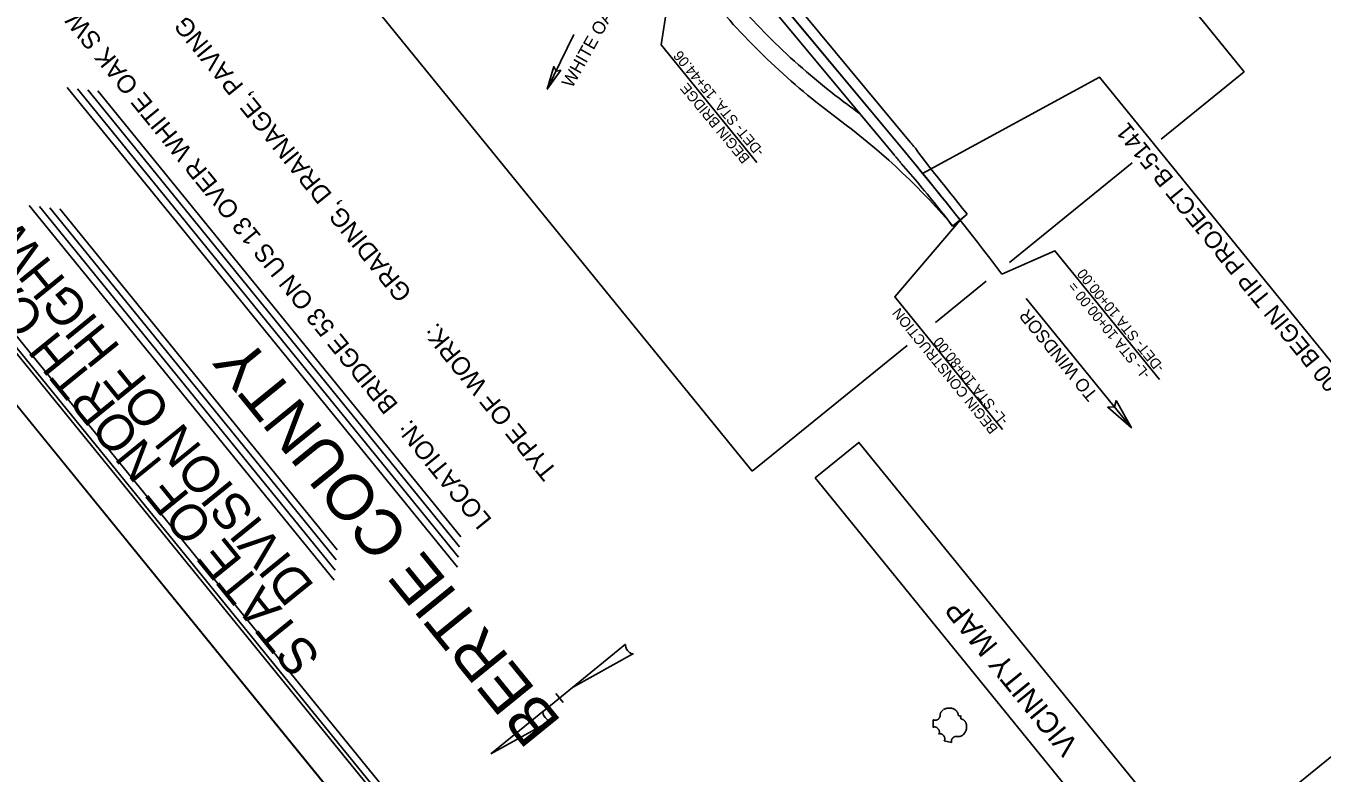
# Model space of a CAD drawing. Extents: x 2596486 to 2602076, y 851390 to 856110.
# Drawn here: x 2597251 to 2598768, y 852253 to 853129 of the extents above; entities that cross this region are included whole.
import ezdxf

# ---------------------------------------------------------------- set-up
doc = ezdxf.new("R2010")
doc.units = 0
for name, color, linetype in [('Default', 7, 'Continuous'), ('Old_Level_1', 7, 'Continuous'), ('Prop Dimension', 7, 'Continuous'), ('Prop Dimension Text', 7, 'Continuous'), ('Prop Horizontal Alignment', 7, 'Continuous'), ('Prop North Arrow for Plan Sheets CELL', 7, 'Continuous'), ('Prop Shade Light', 7, 'Continuous'), ('Prop Terminator CELL', 7, 'Continuous'), ('Sheet Cutting Line CELL', 7, 'Continuous'), ('Sheet Data Field CELL', 7, 'Continuous'), ('Sheet Data Text CELL', 7, 'Continuous'), ('Sheet Plot Border Inside CELL', 7, 'Continuous'), ('Sheet Plot Border Outside CELL', 7, 'Continuous'), ('Sheet Title CELL', 7, 'Continuous')]:
    doc.layers.add(name, color=color, linetype=linetype)

msp = doc.modelspace()

# ---------------------------------------------------------------- linework, layer by layer
at = {"layer": 'Default'}
for p, q in [((2598320.8, 852320.3), (2598320.9, 852320.7)), ((2598320.8, 852319.8), (2598320.8, 852320.3)), ((2598320.9, 852321.6), (2598321, 852322)), ((2598320.9, 852321.3), (2598320.9, 852321.6)), ((2598320.9, 852320.7), (2598320.9, 852321.3)), ((2598321, 852322), (2598321.1, 852322.6)), ((2598321.1, 852322.9), (2598321.2, 852323.2)), ((2598321.1, 852322.6), (2598321.1, 852322.9)), ((2598321.2, 852323.2), (2598321.4, 852323.6)), ((2598321.4, 852323.6), (2598321.5, 852323.9)), ((2598321.5, 852323.9), (2598321.6, 852324.1)), ((2598321.6, 852324.1), (2598321.9, 852324.7)), ((2598321.9, 852324.7), (2598322.3, 852325.2)), ((2598322.3, 852325.2), (2598322.4, 852325.5)), ((2598322.4, 852325.5), (2598322.9, 852326)), ((2598322.9, 852326), (2598323.1, 852326.3)), ((2598323.1, 852326.3), (2598323.6, 852326.8)), ((2598323.6, 852326.8), (2598324.3, 852327.3)), ((2598324.9, 852327.7), (2598325.7, 852328.2)), ((2598325.7, 852328.2), (2598326.2, 852328.4)), ((2598326.2, 852328.4), (2598326.8, 852328.7)), ((2598326.8, 852328.7), (2598327.3, 852328.9)), ((2598327.3, 852328.9), (2598328.2, 852329.1)), ((2598328.2, 852329.1), (2598328.8, 852329.3)), ((2598328.8, 852329.3), (2598329.6, 852329.4)), ((2598329.6, 852329.4), (2598330.1, 852329.5)), ((2598330.1, 852329.5), (2598330.6, 852329.5)), ((2598330.6, 852329.5), (2598331.2, 852329.6)), ((2598331.2, 852329.6), (2598331.9, 852329.6)), ((2598331.9, 852329.6), (2598332.7, 852329.5)), ((2598332.7, 852329.5), (2598333.3, 852329.5)), ((2598333.3, 852329.5), (2598334, 852329.4)), ((2598334, 852329.4), (2598334.4, 852329.3)), ((2598334.4, 852329.3), (2598335, 852329.1)), ((2598335, 852329.1), (2598335.8, 852328.9)), ((2598335.8, 852328.9), (2598336.4, 852328.6)), ((2598336.4, 852328.6), (2598337, 852328.4)), ((2598337, 852328.4), (2598337.5, 852328.1)), ((2598337.5, 852328.1), (2598338.1, 852327.8)), ((2598338.1, 852327.8), (2598338.9, 852327.2)), ((2598338.9, 852327.2), (2598339.2, 852326.9)), ((2598339.2, 852326.9), (2598339.6, 852326.6)), ((2598339.6, 852326.6), (2598339.9, 852326.3)), ((2598339.9, 852326.3), (2598340.2, 852326)), ((2598340.2, 852326), (2598340.5, 852325.6)), ((2598340.5, 852325.6), (2598340.8, 852325.1)), ((2598340.8, 852325.1), (2598341.1, 852324.7)), ((2598341.1, 852324.7), (2598341.3, 852324.2)), ((2598341.3, 852324.2), (2598341.6, 852323.7)), ((2598341.6, 852323.7), (2598341.7, 852323.1)), ((2598341.7, 852323.1), (2598341.9, 852322.6)), ((2598341.9, 852322.6), (2598342, 852321.5)), ((2598342, 852321.5), (2598342, 852321.3)), ((2598342, 852321.3), (2598342.1, 852321.1)), ((2598342.1, 852321.1), (2598342.3, 852320.9)), ((2598342.3, 852320.9), (2598342.5, 852320.7)), ((2598342.5, 852320.7), (2598342.9, 852320.5)), ((2598342.9, 852320.5), (2598343.1, 852320.4)), ((2598343.1, 852320.4), (2598343.4, 852320.3)), ((2598343.4, 852320.3), (2598343.6, 852320.3)), ((2598344.8, 852320.2), (2598345, 852320.3)), ((2598345, 852320.3), (2598345.3, 852320.4)), ((2598345.3, 852320.4), (2598345.6, 852320.5)), ((2598345.6, 852320.5), (2598345.3, 852320.2)), ((2598312.8, 852306.9), (2598312.7, 852315.9)), ((2598312.7, 852315.9), (2598312.8, 852315.8)), ((2598312.8, 852315.8), (2598313.2, 852315.7)), ((2598312.9, 852307), (2598312.8, 852306.9)), ((2598313.1, 852307.1), (2598312.9, 852307)), ((2598313.4, 852307.3), (2598313.1, 852307.1)), ((2598313.2, 852315.7), (2598313.6, 852315.5)), ((2598313.7, 852307.4), (2598313.4, 852307.3)), ((2598313.6, 852315.5), (2598314.1, 852315.4)), ((2598314, 852307.4), (2598313.7, 852307.4)), ((2598314.3, 852307.4), (2598314, 852307.4)), ((2598314.1, 852315.4), (2598314.4, 852315.3)), ((2598314.7, 852307.4), (2598314.3, 852307.4)), ((2598314.4, 852315.3), (2598314.7, 852315.3)), ((2598314.7, 852315.3), (2598315, 852315.3)), ((2598315.1, 852307.4), (2598314.7, 852307.4)), ((2598315, 852315.3), (2598315.2, 852315.3)), ((2598315.5, 852307.3), (2598315.1, 852307.4)), ((2598315.2, 852315.3), (2598315.6, 852315.3)), ((2598315.8, 852307.2), (2598315.5, 852307.3)), ((2598315.6, 852315.3), (2598315.9, 852315.3)), ((2598316.3, 852307), (2598315.8, 852307.2)), ((2598315.9, 852315.3), (2598316.3, 852315.4)), ((2598316.3, 852315.4), (2598316.6, 852315.5)), ((2598316.6, 852306.8), (2598316.3, 852307)), ((2598316.6, 852315.5), (2598317.1, 852315.6)), ((2598317, 852306.6), (2598316.6, 852306.8)), ((2598317.3, 852306.3), (2598317, 852306.6)), ((2598317.1, 852315.6), (2598317.5, 852315.8)), ((2598317.6, 852306.1), (2598317.3, 852306.3)), ((2598317.5, 852315.8), (2598317.8, 852315.9)), ((2598317.9, 852305.9), (2598317.6, 852306.1)), ((2598317.8, 852315.9), (2598318.3, 852316.3)), ((2598318.2, 852305.6), (2598317.9, 852305.9)), ((2598318.4, 852305.3), (2598318.2, 852305.6)), ((2598318.3, 852316.3), (2598318.6, 852316.4)), ((2598318.6, 852305), (2598318.4, 852305.3)), ((2598318.6, 852316.4), (2598318.8, 852316.6)), ((2598318.8, 852316.6), (2598319, 852316.8)), ((2598319, 852316.8), (2598319.2, 852317)), ((2598319.2, 852317), (2598319.4, 852317.3)), ((2598319.4, 852317.3), (2598319.6, 852317.5)), ((2598319.6, 852317.5), (2598319.8, 852317.8)), ((2598319.8, 852317.8), (2598320.1, 852318.1)), ((2598320.1, 852318.1), (2598320.3, 852318.5)), ((2598320.3, 852318.5), (2598320.5, 852319.1)), ((2598320.5, 852319.1), (2598320.8, 852319.8)), ((2598343.6, 852320.3), (2598343.9, 852320.2)), ((2598343.9, 852320.2), (2598344.2, 852320.2)), ((2598344.2, 852320.2), (2598344.4, 852320.2)), ((2598344.4, 852320.2), (2598344.8, 852320.2)), ((2598345, 852319), (2598344.9, 852318.7)), ((2598344.9, 852318.7), (2598344.9, 852318.3)), ((2598344.9, 852318.3), (2598345, 852318)), ((2598345.1, 852319.6), (2598345, 852319.3)), ((2598345, 852319.3), (2598345, 852319)), ((2598345, 852318), (2598345, 852317.7)), ((2598345, 852317.7), (2598345.1, 852317.5)), ((2598345.2, 852319.9), (2598345.1, 852319.6)), ((2598345.1, 852317.5), (2598345.2, 852317.3)), ((2598345.3, 852320.2), (2598345.2, 852319.9)), ((2598345.2, 852317.3), (2598345.3, 852317.1)), ((2598345.3, 852317.1), (2598345.4, 852317)), ((2598345.4, 852317), (2598345.6, 852316.8)), ((2598345.6, 852316.8), (2598346, 852316.7)), ((2598346, 852316.7), (2598346.4, 852316.6)), ((2598346.4, 852316.6), (2598346.7, 852316.5)), ((2598346.7, 852316.5), (2598347.1, 852316.3)), ((2598347.1, 852316.3), (2598347.4, 852316.2)), ((2598347.4, 852316.2), (2598347.7, 852316)), ((2598347.7, 852316), (2598348.1, 852315.8)), ((2598348.1, 852315.8), (2598348.5, 852315.5)), ((2598348.5, 852315.5), (2598348.8, 852315.2)), ((2598348.8, 852315.2), (2598349.1, 852315)), ((2598349.1, 852315), (2598349.4, 852314.7)), ((2598349.4, 852314.7), (2598349.7, 852314.4)), ((2598349.7, 852314.4), (2598349.9, 852314.1)), ((2598349.9, 852314.1), (2598350.1, 852313.8)), ((2598350.1, 852313.8), (2598350.4, 852313.4)), ((2598350.4, 852313.4), (2598350.6, 852312.9)), ((2598350.6, 852312.9), (2598350.8, 852312.5)), ((2598350.8, 852312.5), (2598351, 852312.1)), ((2598351, 852312.1), (2598351.2, 852311.6)), ((2598351.2, 852311.6), (2598351.4, 852311.1)), ((2598351.4, 852311.1), (2598351.6, 852310.4)), ((2598351.6, 852305.2), (2598351.4, 852304.2)), ((2598351.6, 852310.4), (2598351.7, 852309.9)), ((2598351.7, 852305.8), (2598351.6, 852305.2)), ((2598351.7, 852309.9), (2598351.8, 852309.1)), ((2598351.9, 852306.7), (2598351.7, 852305.8)), ((2598351.8, 852309.1), (2598351.9, 852308.1)), ((2598351.9, 852308.1), (2598351.9, 852307.3)), ((2598351.9, 852307.3), (2598351.9, 852306.7)), ((2598318.8, 852304.8), (2598318.6, 852305)), ((2598319.1, 852304.5), (2598318.8, 852304.8)), ((2598319.2, 852304.2), (2598319.1, 852304.5)), ((2598319.4, 852303.8), (2598319.2, 852304.2)), ((2598319.5, 852299.3), (2598319.2, 852299)), ((2598319.2, 852299), (2598319.4, 852299.3)), ((2598319.6, 852303.5), (2598319.4, 852303.8)), ((2598319.4, 852299.3), (2598319.5, 852299.4)), ((2598319.5, 852299.4), (2598319.7, 852299.6)), ((2598319.6, 852299.4), (2598319.5, 852299.3)), ((2598319.7, 852303.1), (2598319.6, 852303.5)), ((2598320.1, 852299.5), (2598319.6, 852299.4)), ((2598319.8, 852302.9), (2598319.7, 852303.1)), ((2598319.7, 852299.6), (2598319.8, 852299.8)), ((2598319.9, 852302.6), (2598319.8, 852302.9)), ((2598319.8, 852299.8), (2598319.9, 852300.1)), ((2598320.1, 852301.9), (2598319.9, 852302.6)), ((2598319.9, 852300.1), (2598320, 852300.4)), ((2598320, 852300.4), (2598320.1, 852300.9)), ((2598320.1, 852301.4), (2598320.1, 852301.9)), ((2598320.1, 852301.1), (2598320.1, 852301.4)), ((2598320.1, 852300.9), (2598320.1, 852301.1)), ((2598320.3, 852299.5), (2598320.1, 852299.5)), ((2598320.5, 852299.6), (2598320.3, 852299.5)), ((2598321, 852299.6), (2598320.5, 852299.6)), ((2598321.5, 852299.5), (2598321, 852299.6)), ((2598321.8, 852299.4), (2598321.5, 852299.5)), ((2598322.2, 852299.3), (2598321.8, 852299.4)), ((2598322.7, 852299.1), (2598322.2, 852299.3)), ((2598323, 852298.9), (2598322.7, 852299.1)), ((2598323.4, 852298.7), (2598323, 852298.9)), ((2598323.7, 852298.5), (2598323.4, 852298.7)), ((2598324.3, 852297.9), (2598323.7, 852298.5)), ((2598324.8, 852297.4), (2598324.3, 852297.9)), ((2598325.3, 852296.9), (2598324.8, 852297.4)), ((2598325.6, 852296.3), (2598325.3, 852296.9)), ((2598325.5, 852291.2), (2598325.8, 852291.4)), ((2598334.4, 852289.3), (2598325.5, 852291.2)), ((2598325.9, 852295.7), (2598325.6, 852296.3)), ((2598325.8, 852291.4), (2598326, 852291.7)), ((2598326.2, 852295.2), (2598325.9, 852295.7)), ((2598326, 852291.7), (2598326.1, 852291.8)), ((2598326.1, 852291.8), (2598326.3, 852292.2)), ((2598326.3, 852294.6), (2598326.2, 852295.2)), ((2598326.4, 852294.1), (2598326.3, 852294.6)), ((2598326.3, 852292.2), (2598326.4, 852292.6)), ((2598326.5, 852293.7), (2598326.4, 852294.1)), ((2598326.4, 852292.6), (2598326.5, 852293.2)), ((2598326.5, 852293.2), (2598326.5, 852293.7)), ((2598334.2, 852291.5), (2598334.1, 852291)), ((2598334.1, 852291), (2598334.1, 852290.6)), ((2598334.1, 852290.6), (2598334.2, 852290.3)), ((2598334.3, 852291.9), (2598334.2, 852291.5)), ((2598334.2, 852290.3), (2598334.2, 852289.9)), ((2598334.4, 852292.4), (2598334.3, 852291.9)), ((2598334.6, 852292.9), (2598334.4, 852292.4)), ((2598334.8, 852293.3), (2598334.6, 852292.9)), ((2598335, 852293.7), (2598334.8, 852293.3)), ((2598335.3, 852294), (2598335, 852293.7)), ((2598335.6, 852294.4), (2598335.3, 852294)), ((2598335.9, 852294.8), (2598335.6, 852294.4)), ((2598336.2, 852295), (2598335.9, 852294.8)), ((2598336.6, 852295.3), (2598336.2, 852295)), ((2598337, 852295.6), (2598336.6, 852295.3)), ((2598337.4, 852295.8), (2598337, 852295.6)), ((2598337.7, 852295.9), (2598337.4, 852295.8)), ((2598338.1, 852296.1), (2598337.7, 852295.9)), ((2598338.5, 852296.2), (2598338.1, 852296.1)), ((2598338.9, 852296.3), (2598338.5, 852296.2)), ((2598339.2, 852296.3), (2598338.9, 852296.3)), ((2598339.6, 852296.4), (2598339.2, 852296.3)), ((2598340, 852296.4), (2598339.6, 852296.4)), ((2598340.4, 852296.4), (2598340, 852296.4)), ((2598340.9, 852296.3), (2598340.4, 852296.4)), ((2598341.4, 852296.2), (2598340.9, 852296.3)), ((2598341.9, 852296.1), (2598341.4, 852296.2)), ((2598342.4, 852296.1), (2598341.9, 852296.1)), ((2598342.9, 852296.1), (2598342.4, 852296.1)), ((2598343.4, 852296.2), (2598342.9, 852296.1)), ((2598343.8, 852296.2), (2598343.4, 852296.2)), ((2598344.3, 852296.3), (2598343.8, 852296.2)), ((2598344.8, 852296.5), (2598344.3, 852296.3)), ((2598345.3, 852296.7), (2598344.8, 852296.5)), ((2598345.6, 852296.8), (2598345.3, 852296.7)), ((2598346.1, 852297), (2598345.6, 852296.8)), ((2598346.6, 852297.3), (2598346.1, 852297)), ((2598347.1, 852297.7), (2598346.6, 852297.3)), ((2598347.4, 852297.9), (2598347.1, 852297.7)), ((2598347.9, 852298.3), (2598347.4, 852297.9)), ((2598348.3, 852298.7), (2598347.9, 852298.3)), ((2598348.7, 852299.2), (2598348.3, 852298.7)), ((2598349, 852299.5), (2598348.7, 852299.2)), ((2598349.4, 852300), (2598349, 852299.5)), ((2598349.6, 852300.3), (2598349.4, 852300)), ((2598349.9, 852300.8), (2598349.6, 852300.3)), ((2598350.2, 852301.3), (2598349.9, 852300.8)), ((2598350.5, 852301.9), (2598350.2, 852301.3)), ((2598350.8, 852302.3), (2598350.5, 852301.9)), ((2598351, 852303), (2598350.8, 852302.3)), ((2598351.2, 852303.5), (2598351, 852303)), ((2598351.4, 852304.2), (2598351.2, 852303.5)), ((2598334.2, 852289.9), (2598334.3, 852289.5)), ((2598334.3, 852289.5), (2598334.4, 852289.3))]:
    msp.add_line(p, q, dxfattribs=at)
at = {"layer": 'Old_Level_1'}
for p, q in [((2598676.9, 853075), (2597979.3, 853933.2)), ((2598101, 852606.9), (2597403.5, 853465.1)), ((2597891.9, 853118.6), (2597861, 853054.4)), ((2598676.9, 853075), (2598579.6, 852995.9)), ((2598545.9, 852968.4), (2598402, 852851.5)), ((2598374.9, 852829.5), (2598315.4, 852781.2)), ((2598421.7, 852809.4), (2598544.9, 852657.9)), ((2598282.2, 852754.2), (2598101, 852606.9))]:
    msp.add_line(p, q, dxfattribs=at)
msp.add_lwpolyline([(2598918.6, 852562.8), (2598507.6, 853068.5), (2598300.4, 852955.8)], dxfattribs=at)
msp.add_lwpolyline([(2598563.8, 852120.3), (2598174.7, 852599.1), (2598225.8, 852640.7), (2598614.9, 852161.8)], close=True, dxfattribs=at)
at = {"layer": 'Prop Dimension'}
for points in [[(2598393.9, 852655.9), (2598267.7, 852811.3), (2598344.2, 852901.2)], [(2598577.9, 852714.4), (2598455.3, 852865.1), (2598393.1, 852837.9)]]:
    msp.add_lwpolyline(points, dxfattribs=at)
at = {"layer": 'Prop Dimension Text'}
msp.add_lwpolyline([(2598106.5, 852968.5), (2597994.5, 853106.3), (2598012.8, 853224.2)], dxfattribs=at)
at = {"layer": 'Prop Horizontal Alignment'}
msp.add_line((2598276.5, 852984.9), (2597890.8, 853449.4), dxfattribs=at)
msp.add_arc((2595067.5, 850320.2), 4171.2, 37.1289, 39.7067, dxfattribs=at)
at = {"layer": 'Prop North Arrow for Plan Sheets CELL'}
for p, q in [((2597952.6, 852404.2), (2597890.6, 852353.7)), ((2597890.6, 852353.7), (2597961.9, 852393.3)), ((2597890.6, 852353.7), (2597856, 852325.6)), ((2597879.5, 852336), (2597870.9, 852346.6)), ((2597875.8, 852340.6), (2597879.6, 852336)), ((2597879.6, 852336), (2597879.6, 852335.9)), ((2597794.8, 852275.8), (2597857.9, 852327.1)), ((2597857.9, 852327.1), (2597856.1, 852325.6)), ((2597864.8, 852314.7), (2597794.9, 852275.8)), ((2597794.8, 852275.8), (2597794.9, 852275.8)), ((2597794.8, 852275.8), (2597794.9, 852275.8))]:
    msp.add_line(p, q, dxfattribs=at)
for centre, start_param, end_param in [((2597957.6, 852399.1), 0.201328, 3.141593), ((2597861, 852320.6), 0.216388, 2.908219)]:
    msp.add_ellipse(centre, major_axis=(-4.5, 5.61), ratio=0.461098, start_param=start_param, end_param=end_param, dxfattribs=at)
at = {"layer": 'Prop Shade Light'}
for p, q in [((2598276.5, 852984.9), (2598069.3, 853234.4)), ((2598069.3, 853234.4), (2598276.5, 852984.9)), ((2598285.7, 852992.6), (2598078.6, 853242.1)), ((2598060.1, 853226.7), (2598267.3, 852977.3)), ((2598267.3, 852977.3), (2598227.8, 853024.8)), ((2598308.7, 852962.6), (2598293.8, 852982.8)), ((2598275.3, 852967.6), (2598291.8, 852948.8)), ((2598291.8, 852948.8), (2598275.3, 852967.6)), ((2598330.7, 852900.3), (2598335.6, 852894.2)), ((2598335.5, 852894.1), (2598352.7, 852908.1)), ((2598335.6, 852894.2), (2598344.2, 852901.2)), ((2598344.2, 852901.2), (2598352.5, 852908))]:
    msp.add_line(p, q, dxfattribs=at)
msp.add_lwpolyline([(2598352.5, 852908), (2598352.5, 852908)], dxfattribs=at)
for centre, radius, start, end in [((2598702.4, 853697.7), 823, 219.7067, 233.4707), ((2598702.4, 853697.7), 843, 219.7067, 233.4707), ((2597710.7, 852359), 843, 52.1621, 53.4707), ((2597710.7, 852359), 823, 41.1205, 53.4707), ((2595076.8, 850327.8), 4171.2, 39.5327, 39.7067), ((2595067.5, 850320.2), 4159.2, 39.5337, 39.7067), ((2595067.5, 850320.2), 4159.2, 39.5337, 39.7067), ((2595067.5, 850320.2), 4171.2, 38.2278, 39.7067), ((2595067.5, 850320.2), 4171.2, 38.2278, 39.7067), ((2595067.5, 850320.2), 4181.9, 38.2302, 39.1893), ((2595067.5, 850320.2), 4160, 38.2252, 39.1893), ((2595067.5, 850320.2), 4160, 38.2252, 39.1893)]:
    msp.add_arc(centre, radius, start, end, dxfattribs=at)
at = {"layer": 'Prop Terminator CELL'}
for points in [[(2597876.9, 853076.7), (2597861, 853054.4), (2597868.5, 853080.9), (2597871.3, 853075.8)], [(2598527, 852689.7), (2598544.9, 852657.9), (2598517.1, 852682), (2598525, 852682.4)]]:
    msp.add_lwpolyline(points, close=True, dxfattribs=at)
at = {"layer": 'Sheet Cutting Line CELL'}
msp.add_line((2598291.5, 851390.2), (2596485.9, 853611.8), dxfattribs=at)
at = {"layer": 'Sheet Plot Border Inside CELL'}
msp.add_lwpolyline([(2599699.1, 852562.7), (2597912.3, 854761.2), (2596520.4, 853629.9), (2598307.2, 851431.4)], close=True, dxfattribs=at)
at = {"layer": 'Sheet Plot Border Outside CELL'}
msp.add_lwpolyline([(2596485.9, 853611.8), (2598291.5, 851390.2), (2599742.7, 852569.6), (2597937, 854791.2)], close=True, dxfattribs=at)
at = {"layer": 'Sheet Title CELL'}
for p, q in [((2597755.9, 852494.4), (2597299.1, 853056.4)), ((2597757.1, 852506.3), (2597311.1, 853055.1)), ((2597758.4, 852518.3), (2597323, 853053.9)), ((2597759.6, 852530.2), (2597335, 853052.7)), ((2597611.4, 852479.2), (2597254.6, 852918.1)), ((2597612.6, 852491.1), (2597266.6, 852916.9)), ((2597613.9, 852503.1), (2597278.5, 852915.6)), ((2597615.1, 852515), (2597290.5, 852914.4)), ((2599207.8, 852621.3), (2598106.2, 851726))]:
    msp.add_line(p, q, dxfattribs=at)
for points in [[(2596547.8, 853603), (2598134.7, 851650.5)], [(2596559.8, 853601.8), (2598082.3, 851728.5)]]:
    msp.add_lwpolyline(points, dxfattribs=at)

# ---------------------------------------------------------------- texts
at = {"layer": 'Old_Level_1'}
for s, height, rotation, p in [('WHITE OAK SWAMP', 15, 60.8082, (2597890.1, 853054.9)), ('-L- STA 11+50.00 BEGIN TIP PROJECT B-5141', 20, 129.1027, (2598904.9, 852569)), ('-DET- STA 10+00.00', 12, 129.1027, (2598584.3, 852728.8)), (' -L- STA 10+00.00 = ', 12, 129.1027, (2598570.4, 852717.4)), ('BEGIN CONSTRUCTION', 12, 129.1027, (2598389.2, 852656.9)), ('TO WINDSOR', 15, 129.1028, (2598506.1, 852697)), ('-L- STA 10+80.00', 12, 129.1027, (2598401.4, 852666.8)), ('VICINITY MAP', 24.949, 129.1028, (2598484.3, 852286.4))]:
    msp.add_text(s, height=height, rotation=rotation, dxfattribs=at).set_placement(p)
at = {"layer": 'Sheet Data Field CELL'}
for s, height, p in [('GRADING, DRAINAGE, PAVING, AND STRUCTURE', 21.25, (2597703.6, 852816.1)), ('BRIDGE 53 ON US 13 OVER WHITE OAK SWAMP ', 21.25, (2597687.3, 852685.1)), ('        BERTIE COUNTY        ', 54, (2597980, 852189))]:
    msp.add_text(s, height=height, rotation=129.1028, dxfattribs=at).set_placement(p)
at = {"layer": 'Sheet Data Text CELL'}
for s, p in [('-DET- STA. 15+44.06', (2598115.7, 852981.8)), (' BEGIN BRIDGE', (2598101.8, 852970.3))]:
    msp.add_text(s, height=12, rotation=129.7066, dxfattribs=at).set_placement(p)
at = {"layer": 'Sheet Title CELL'}
for s, height, p in [('STATE OF NORTH CAROLINA', 42.5, (2597597.1, 852389.1)), ('DIVISION OF HIGHWAYS', 42.5, (2597589.5, 852472.5)), ('TYPE OF WORK:', 21.25, (2597873.7, 852607.2)), ('LOCATION: ', 21.25, (2597797, 852550.1))]:
    msp.add_text(s, height=height, rotation=129.1028, dxfattribs=at).set_placement(p)

doc.saveas('drawing.dxf')
